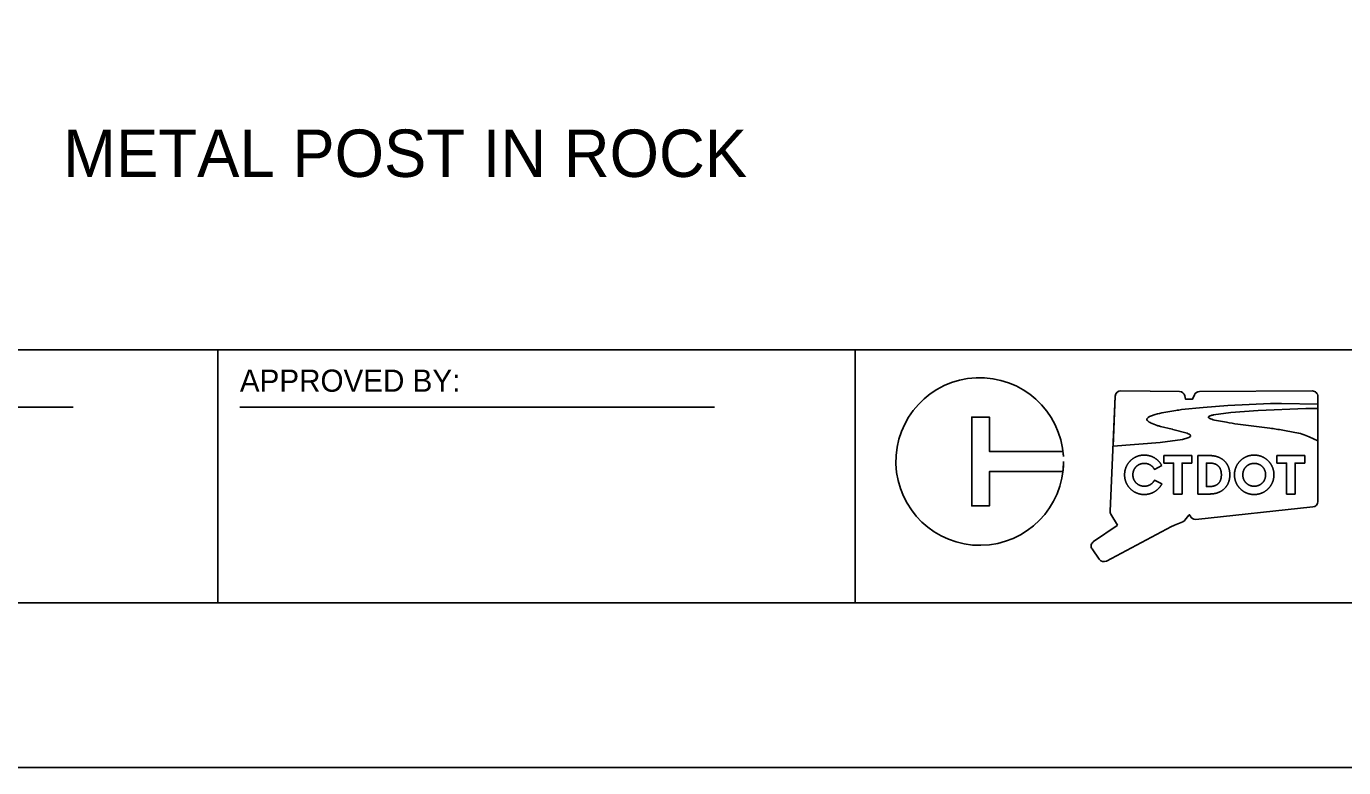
# Model space of a CAD drawing. Extents: x 0 to 2.85, y -0.1 to 1.83.
# Drawn here: x 1.0563 to 1.4727, y 0 to 0.2344 of the extents above; entities that cross this region are included whole.
import ezdxf

# ---------------------------------------------------------------- set-up
doc = ezdxf.new("R2010")
doc.units = 0
for name, color, linetype in [('BDR_Inner_Perimeter', 7, 'Continuous'), ('BDR_Outer_Perimeter', 7, 'Continuous'), ('BDR_Title_Block', 7, 'Continuous'), ('CT_CSHT_GeneralLabel', 7, 'Continuous')]:
    doc.layers.add(name, color=color, linetype=linetype)

msp = doc.modelspace()

# ---------------------------------------------------------------- linework, layer by layer
at = {"layer": 'BDR_Inner_Perimeter'}
msp.add_lwpolyline([(0.1353943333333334, 1.781248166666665), (2.7812276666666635, 1.781248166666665), (2.7812276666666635, 0.052081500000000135), (0.1353943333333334, 0.052081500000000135)], close=True, dxfattribs=at)
at = {"layer": 'BDR_Outer_Perimeter'}
msp.add_lwpolyline([(0, 0), (2.8333276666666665, 0), (2.833327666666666, 1.8333296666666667), (0, 1.8333296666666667)], close=True, dxfattribs=at)
at = {"layer": 'BDR_Title_Block'}
for p, q in [((2.7812276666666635, 0.13208150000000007), (0.13539433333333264, 0.13208150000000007)), ((1.1168526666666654, 0.052081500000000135), (1.1168526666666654, 0.13208150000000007)), ((1.318310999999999, 0.05208150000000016), (1.318310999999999, 0.13208150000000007)), ((1.3183109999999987, 0.05208150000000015), (1.3183109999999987, 0.13208150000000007)), ((1.3183109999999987, 0.05208150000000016), (1.3183109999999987, 0.13208150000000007)), ((1.398868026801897, 0.08115415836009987), (1.400531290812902, 0.11750915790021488)), ((1.4022794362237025, 0.11915588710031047), (1.4208470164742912, 0.1188957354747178)), ((1.4022794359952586, 0.1191558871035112), (1.4208470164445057, 0.118895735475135)), ((1.4225087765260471, 0.1175387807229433), (1.4227206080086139, 0.11657000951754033)), ((1.4249867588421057, 0.11657000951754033), (1.4255451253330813, 0.1178911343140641)), ((1.4271262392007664, 0.11894503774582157), (1.4628427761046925, 0.11912118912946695)), ((1.4271262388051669, 0.11894503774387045), (1.4628427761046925, 0.11912118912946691)), ((1.4645770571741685, 0.11739325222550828), (1.464534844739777, 0.08407889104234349)), ((0.921030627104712, 0.11402230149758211), (1.0710306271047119, 0.11402230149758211)), ((1.1237704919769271, 0.11402230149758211), (1.273770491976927, 0.11402230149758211)), ((1.4197017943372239, 0.11296056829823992), (1.415911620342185, 0.1123088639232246)), ((1.4227206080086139, 0.11657000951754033), (1.4249867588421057, 0.11657000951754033)), ((1.4109569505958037, 0.11077303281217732), (1.4106753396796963, 0.11053092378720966)), ((1.4106849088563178, 0.10973959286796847), (1.410993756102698, 0.1094867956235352)), ((1.4131784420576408, 0.11164539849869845), (1.4116649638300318, 0.11116726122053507)), ((1.4121354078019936, 0.10882658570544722), (1.4137533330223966, 0.10821263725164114)), ((1.4302260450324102, 0.11051681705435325), (1.4300834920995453, 0.11059713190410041)), ((1.430106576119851, 0.11105270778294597), (1.4305659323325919, 0.11125335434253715)), ((1.435652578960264, 0.10921797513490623), (1.4318782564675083, 0.10991721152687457)), ((1.4493650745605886, 0.10733566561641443), (1.4392681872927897, 0.10864843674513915)), ((1.4147914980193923, 0.10789543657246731), (1.4185404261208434, 0.10701613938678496)), ((1.4187174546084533, 0.1069713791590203), (1.4232963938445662, 0.10572912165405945)), ((1.4238869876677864, 0.10543336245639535), (1.424256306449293, 0.10514458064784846)), ((1.4242587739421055, 0.10470847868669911), (1.4241371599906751, 0.10461114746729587)), ((1.4573152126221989, 0.10603093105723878), (1.453479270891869, 0.10670633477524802)), ((1.412908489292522, 0.09430650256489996), (1.4152447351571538, 0.09550445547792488)), ((1.4152447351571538, 0.08970436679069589), (1.412908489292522, 0.0909023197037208)), ((1.4444416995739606, 0.08899557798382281), (1.4444416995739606, 0.08899557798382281)), ((1.4096936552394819, 0.08636115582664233), (1.4096936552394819, 0.08636115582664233)), ((1.4444416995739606, 0.08636115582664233), (1.4444416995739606, 0.08636115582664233)), ((1.4011960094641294, 0.0767004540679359), (1.3991106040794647, 0.0801899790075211)), ((1.423831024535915, 0.07987901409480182), (1.422525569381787, 0.07824387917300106)), ((1.424176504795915, 0.07961852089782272), (1.42409221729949, 0.07983849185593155)), ((1.462990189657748, 0.08242493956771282), (1.4259690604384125, 0.0785197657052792)), ((1.3936518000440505, 0.07149451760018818), (1.401165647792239, 0.07656422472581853)), ((1.4183312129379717, 0.07622410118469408), (1.3976986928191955, 0.06533493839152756)), ((1.4218366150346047, 0.07772592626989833), (1.4192574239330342, 0.07665893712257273)), ((1.3954751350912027, 0.06587761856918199), (1.3932106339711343, 0.0691424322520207))]:
    msp.add_line(p, q, dxfattribs=at)
for points in [[(1.4234794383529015, 0.10427150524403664), (1.421729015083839, 0.1037711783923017), (1.4147375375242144, 0.10285292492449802), (1.3998084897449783, 0.10171044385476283), (1.4005312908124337, 0.11750915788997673)], [(1.4225087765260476, 0.11753878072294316), (1.4227206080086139, 0.11657000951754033), (1.4249867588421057, 0.11657000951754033), (1.4255451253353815, 0.11789113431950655)], [(1.464577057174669, 0.11739325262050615), (1.464573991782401, 0.11497402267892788), (1.4530585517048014, 0.1151562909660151)], [(1.4495821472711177, 0.11511054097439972), (1.4360771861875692, 0.11454102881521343), (1.428287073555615, 0.11392805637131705), (1.4214346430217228, 0.11320119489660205)], [(1.4316149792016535, 0.11154829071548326), (1.4370765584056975, 0.11229746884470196), (1.4456637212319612, 0.1128915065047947), (1.460734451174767, 0.11351971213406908), (1.4645721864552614, 0.11354924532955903), (1.4645593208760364, 0.1033956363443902), (1.4618567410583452, 0.10462392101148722)], [(1.3839880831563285, 0.09361217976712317), (1.3607277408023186, 0.09361217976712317), (1.3607277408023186, 0.08274997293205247), (1.355144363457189, 0.08274997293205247), (1.355144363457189, 0.11086989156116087), (1.3607277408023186, 0.11086989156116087), (1.3607277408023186, 0.10000768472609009), (1.3839881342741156, 0.10000768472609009)], [(1.4302447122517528, 0.09868785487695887), (1.4266615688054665, 0.09868785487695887), (1.4266615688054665, 0.08652091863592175), (1.4302447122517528, 0.08652091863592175)], [(1.4302447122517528, 0.08888906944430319), (1.4293472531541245, 0.08888906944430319), (1.4293472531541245, 0.09631970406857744), (1.4302447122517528, 0.09631970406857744)]]:
    msp.add_lwpolyline(points, dxfattribs=at)
for points in [[(1.4247180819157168, 0.09868785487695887), (1.4159135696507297, 0.09868785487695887), (1.4159135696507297, 0.09631970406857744), (1.4189786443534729, 0.09631970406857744), (1.4189786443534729, 0.08652091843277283), (1.4216530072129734, 0.08652091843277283), (1.4216530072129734, 0.09631970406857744), (1.4247180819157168, 0.09631970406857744)], [(1.4604383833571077, 0.09868785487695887), (1.4516338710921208, 0.09868785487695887), (1.4516338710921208, 0.09631970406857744), (1.454698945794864, 0.09631970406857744), (1.454698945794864, 0.08652091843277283), (1.4573733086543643, 0.08652091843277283), (1.4573733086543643, 0.09631970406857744), (1.4604383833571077, 0.09631970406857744)]]:
    msp.add_lwpolyline(points, close=True, dxfattribs=at)
for centre, radius, start, end in [((1.3576789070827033, 0.09680993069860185), 0.026502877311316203, 3.363017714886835, 0), ((1.402255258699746, 0.11743028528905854), 0.001725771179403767, 89.19728521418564, 177.38050914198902), ((1.402255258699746, 0.11743028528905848), 0.001725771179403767, 89.19728505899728, 177.38050914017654), ((1.4208228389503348, 0.1171701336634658), 0.001725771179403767, 12.334165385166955, 89.19727847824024), ((1.4208228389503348, 0.11717013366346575), 0.001725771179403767, 12.334164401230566, 89.19727846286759), ((1.427134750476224, 0.11721928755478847), 0.001725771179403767, 90.2825895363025, 157.08890346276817), ((1.4271347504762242, 0.11721928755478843), 0.001725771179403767, 90.28258949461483, 157.08890384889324), ((1.46285128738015, 0.11739543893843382), 0.001725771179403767, 359.9274140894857, 90.28257636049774), ((1.46285128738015, 0.11739543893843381), 0.001725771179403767, 359.9274140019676, 90.28257636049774), ((1.4242916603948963, 0.08626688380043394), 0.027085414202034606, 96.05492396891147, 99.75636320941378), ((1.4521092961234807, 0.05518373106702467), 0.05998007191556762, 89.09318866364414, 92.41476599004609), ((1.4110120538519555, 0.1101392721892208), 0.0005164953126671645, 130.6865987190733, 230.6990332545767), ((1.4122731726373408, 0.10924205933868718), 0.002018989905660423, 107.53234228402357, 130.68659871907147), ((1.4135891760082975, 0.1126576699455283), 0.004097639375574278, 230.6990332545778, 249.21992301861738), ((1.4194261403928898, 0.09186916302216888), 0.02073965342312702, 99.75636320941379, 107.53234228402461), ((1.4302085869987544, 0.11081916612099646), 0.00025484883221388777, 113.59568093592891, 240.6029286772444), ((1.4328532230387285, 0.11517986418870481), 0.005352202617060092, 240.6029286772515, 259.5042992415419), ((1.4321542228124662, 0.10761715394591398), 0.003967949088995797, 97.81065596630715, 113.59568093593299), ((1.4480258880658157, 0.1760063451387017), 0.06792484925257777, 259.50429924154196, 262.59210694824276), ((1.4166665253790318, 0.11588971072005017), 0.008211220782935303, 249.2199230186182, 256.8000863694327), ((1.4173331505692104, 0.10186885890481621), 0.005286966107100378, 74.82112559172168, 76.80008636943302), ((1.4228597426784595, 0.10411963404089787), 0.0016676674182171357, 51.97704538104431, 74.82111769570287), ((1.4229630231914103, 0.10607821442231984), 0.0018790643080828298, 285.9516272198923, 308.67131407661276), ((1.4240850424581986, 0.10492555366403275), 0.0002780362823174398, 308.67131407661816, 51.97704538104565), ((1.4374375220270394, 0.015597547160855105), 0.092510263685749, 80.01414354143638, 82.59210694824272), ((1.4540386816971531, 0.08742194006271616), 0.01889524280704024, 65.55886889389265, 80.0141435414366), ((1.3576861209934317, 0.09681014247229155), 0.026495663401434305, 3.363475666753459, 6.931448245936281), ((1.3576861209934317, 0.09681014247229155), 0.026495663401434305, 353.0676358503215, 359.99954204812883), ((1.4628091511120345, 0.08414118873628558), 0.001725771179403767, 276.0215770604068, 359.9274019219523), ((1.400591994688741, 0.08107528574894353), 0.001725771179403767, 177.38050879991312, 210.86332906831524), ((1.4239500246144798, 0.07978400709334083), 0.00015227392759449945, 20.965610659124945, 141.39691624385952), ((1.4257880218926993, 0.08023601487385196), 0.001725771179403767, 200.9656117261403, 276.0215770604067), ((1.401108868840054, 0.0766483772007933), 0.00010151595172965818, 304.0081374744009, 30.86332906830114), ((1.423448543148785, 0.06652790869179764), 0.010963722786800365, 112.47445835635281, 117.82361241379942), ((1.421176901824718, 0.07932062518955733), 0.0017257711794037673, 292.4744583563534, 321.39691624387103), ((1.394592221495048, 0.07010071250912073), 0.0016813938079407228, 124.0081374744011, 214.7454890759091), ((1.3968931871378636, 0.0668611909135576), 0.001725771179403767, 214.74549081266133, 297.82361241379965)]:
    msp.add_arc(centre, radius, start, end, dxfattribs=at)
for points in [[(1.4065409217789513, 0.09799788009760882), (1.4051349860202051, 0.09716771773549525), (1.4043047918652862, 0.09576187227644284)], [(1.4096936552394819, 0.0988476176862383), (1.4079468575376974, 0.0988280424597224), (1.4065409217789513, 0.09799788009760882)], [(1.4078540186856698, 0.09573365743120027), (1.408665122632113, 0.09620330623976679), (1.4096936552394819, 0.09621319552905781)], [(1.4129783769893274, 0.09792080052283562), (1.411521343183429, 0.09882486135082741), (1.4096936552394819, 0.0988476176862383)], [(1.4096936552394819, 0.09621319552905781), (1.410781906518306, 0.09620259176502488), (1.411615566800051, 0.09569410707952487)], [(1.4152447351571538, 0.09550445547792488), (1.414435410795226, 0.09701673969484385), (1.4129783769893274, 0.09792080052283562)], [(1.4338371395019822, 0.09785868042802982), (1.4323902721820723, 0.09866863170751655), (1.4302447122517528, 0.09868785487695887)], [(1.4302447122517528, 0.09631970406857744), (1.4316621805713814, 0.0963093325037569), (1.4325023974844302, 0.09582447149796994)], [(1.4325023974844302, 0.09582447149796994), (1.4333426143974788, 0.09533961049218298), (1.4337075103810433, 0.09450472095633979)], [(1.4360161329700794, 0.09567873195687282), (1.4352840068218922, 0.09704872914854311), (1.4338371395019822, 0.09785868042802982)], [(1.4412892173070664, 0.09799788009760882), (1.4398833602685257, 0.09716771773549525), (1.4390531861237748, 0.09576187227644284)], [(1.4444416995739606, 0.0988476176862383), (1.442695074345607, 0.0988280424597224), (1.4412892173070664, 0.09799788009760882)], [(1.4426022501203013, 0.09573365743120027), (1.443413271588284, 0.09620330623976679), (1.4444416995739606, 0.09621319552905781)], [(1.4475967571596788, 0.09799788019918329), (1.4461885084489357, 0.09882804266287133), (1.4444416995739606, 0.0988476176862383)], [(1.4444416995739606, 0.09621319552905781), (1.4454797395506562, 0.09620330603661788), (1.4462925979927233, 0.09573365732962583)], [(1.4498375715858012, 0.09576187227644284), (1.449005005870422, 0.09716771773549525), (1.4475967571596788, 0.09799788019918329)], [(1.4043047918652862, 0.09576187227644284), (1.4034745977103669, 0.0943560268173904), (1.4034550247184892, 0.09260940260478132)], [(1.4034550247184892, 0.09260940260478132), (1.403474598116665, 0.09085787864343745), (1.4043047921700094, 0.08944989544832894)], [(1.4060894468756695, 0.09260940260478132), (1.4060996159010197, 0.09364254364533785), (1.406571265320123, 0.09445327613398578)], [(1.4065712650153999, 0.09075849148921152), (1.4060996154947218, 0.09157136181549), (1.4060894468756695, 0.09260940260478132)], [(1.406571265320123, 0.09445327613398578), (1.4070429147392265, 0.09526400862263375), (1.4078540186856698, 0.09573365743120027)], [(1.411615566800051, 0.09569410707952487), (1.412449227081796, 0.0951856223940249), (1.412908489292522, 0.09430650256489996)], [(1.4337075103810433, 0.09450472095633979), (1.434072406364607, 0.0936698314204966), (1.434063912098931, 0.09260937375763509)], [(1.434063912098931, 0.09260937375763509), (1.434072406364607, 0.0915440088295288), (1.4337075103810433, 0.09070699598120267)], [(1.4367495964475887, 0.09260937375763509), (1.4367482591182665, 0.09430873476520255), (1.4360161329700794, 0.09567873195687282)], [(1.4360161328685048, 0.08953298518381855), (1.4367482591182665, 0.09090510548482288), (1.4367495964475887, 0.09260937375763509)], [(1.4390531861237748, 0.09576187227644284), (1.4382230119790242, 0.0943560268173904), (1.4382034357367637, 0.09260940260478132)], [(1.4382034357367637, 0.09260940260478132), (1.4382230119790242, 0.09085787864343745), (1.4390531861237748, 0.08944989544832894)], [(1.440837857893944, 0.09260940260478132), (1.4408480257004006, 0.09364254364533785), (1.4413196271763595, 0.09445327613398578)], [(1.4413196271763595, 0.09075849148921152), (1.4408480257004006, 0.09157136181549), (1.440837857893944, 0.09260940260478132)], [(1.4413196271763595, 0.09445327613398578), (1.4417912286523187, 0.09526400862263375), (1.4426022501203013, 0.09573365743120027)], [(1.4462925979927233, 0.09573365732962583), (1.44710545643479, 0.09526400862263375), (1.4475755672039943, 0.09445327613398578)], [(1.448055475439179, 0.09260940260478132), (1.448022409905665, 0.0910339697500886), (1.4470197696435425, 0.09003130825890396)], [(1.4475755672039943, 0.09445327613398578), (1.4480456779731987, 0.09364254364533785), (1.448055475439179, 0.09260940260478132)], [(1.4498375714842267, 0.0894498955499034), (1.450670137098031, 0.09085787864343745), (1.4506898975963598, 0.09260940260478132)], [(1.4506898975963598, 0.09260940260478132), (1.45067013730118, 0.0943560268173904), (1.4498375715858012, 0.09576187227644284)], [(1.4043047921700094, 0.08944989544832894), (1.4051349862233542, 0.08804191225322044), (1.4065409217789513, 0.08721127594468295)], [(1.4078540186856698, 0.08947549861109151), (1.4070429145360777, 0.08994562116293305), (1.4065712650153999, 0.09075849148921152)], [(1.4096936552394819, 0.08899557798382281), (1.4086651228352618, 0.08900537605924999), (1.4078540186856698, 0.08947549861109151)], [(1.411615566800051, 0.08951469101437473), (1.410781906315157, 0.08900618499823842), (1.4096936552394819, 0.08899557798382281)], [(1.412908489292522, 0.0909023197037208), (1.412449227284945, 0.09002319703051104), (1.411615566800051, 0.08951469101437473)], [(1.4129783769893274, 0.08728797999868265), (1.414435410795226, 0.08819204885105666), (1.4152447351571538, 0.08970436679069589)], [(1.4325023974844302, 0.089384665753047), (1.4316621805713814, 0.08889934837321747), (1.4302447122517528, 0.08888906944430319)], [(1.4337075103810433, 0.09070699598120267), (1.4333426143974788, 0.08986998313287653), (1.4325023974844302, 0.089384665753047)], [(1.4338371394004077, 0.08735045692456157), (1.435284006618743, 0.08816086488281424), (1.4360161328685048, 0.08953298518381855)], [(1.4390531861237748, 0.08944989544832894), (1.4398833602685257, 0.08804191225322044), (1.441289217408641, 0.08721127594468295)], [(1.4426022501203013, 0.08947549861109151), (1.4417912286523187, 0.08994562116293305), (1.4413196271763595, 0.09075849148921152)], [(1.4444416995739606, 0.08899557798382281), (1.443413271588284, 0.08900537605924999), (1.4426022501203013, 0.08947549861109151)], [(1.4470197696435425, 0.09003130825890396), (1.4460171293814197, 0.08902864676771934), (1.4444416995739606, 0.08899557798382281)], [(1.4475967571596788, 0.08721127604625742), (1.449005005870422, 0.08804191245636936), (1.4498375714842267, 0.0894498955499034)], [(1.4065409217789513, 0.08721127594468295), (1.4079468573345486, 0.08638063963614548), (1.4096936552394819, 0.08636115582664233)], [(1.4096936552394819, 0.08636115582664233), (1.411521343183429, 0.08638391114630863), (1.4129783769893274, 0.08728797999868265)], [(1.4302447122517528, 0.08652091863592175), (1.4323902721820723, 0.0865400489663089), (1.4338371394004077, 0.08735045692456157)], [(1.441289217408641, 0.08721127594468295), (1.442695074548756, 0.08638063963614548), (1.4444416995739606, 0.08636115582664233)], [(1.4444416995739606, 0.08636115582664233), (1.4461885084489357, 0.08638063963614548), (1.4475967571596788, 0.08721127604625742)]]:
    msp.add_open_spline(points, degree=2, dxfattribs=at)

# ---------------------------------------------------------------- texts
msp.add_text('APPROVED BY:', height=0.006999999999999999, dxfattribs=at).set_placement((1.1237704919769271, 0.11887066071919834))
at = {"layer": 'CT_CSHT_GeneralLabel'}
msp.add_text('METAL POST IN ROCK', height=0.015, dxfattribs=at).set_placement((1.0679081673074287, 0.18678411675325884))

doc.saveas('drawing.dxf')
